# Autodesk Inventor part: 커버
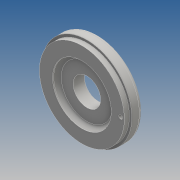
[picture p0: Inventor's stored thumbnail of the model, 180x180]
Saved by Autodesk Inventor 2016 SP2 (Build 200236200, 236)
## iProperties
Created: 2019-08
Part Number: 커버
Material: Generic
Document SubType Name: Modeling
Designer: EZ
Density: 1 g/cm^3
Appearance: Default
Author: EZ
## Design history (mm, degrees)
sketch "스케치1"
  geometry: C1 r 36 at (0, 0); 1 further point
  constraints: 1 centre point, 1 coincident
  dimensions: "d0" = 72 diameter of C1
extrude "돌출1" new body sketch "스케치1" distance "d1" = 9; taper "d2" = 0 deg
fillet "모깎기1" dims "d6" = 3
sketch "스케치3"
  geometry: C1 r 34 at (0, 0); 1 further point
  constraints: 1 centre point, 1 coincident
  dimensions: "d7" = 68 diameter of C1
extrude "돌출3" join sketch "스케치3" distance "d8" = 4; taper "d9" = 0 deg
sketch "스케치4"
  geometry: C1 r 11 at (0, 0); 1 further point
  constraints: 1 centre point, 1 coincident
  dimensions: "d10" = 22 diameter of C1
extrude "돌출4" cut sketch "스케치4" stored distance "d11" = 9; taper "d12" = 0 deg
sketch "스케치5"
  geometry: C1 r 23.5 at (0, 0); 1 further point
  constraints: 1 centre point, 1 coincident
  dimensions: "d13" = 47 diameter of C1
extrude "돌출5" cut sketch "스케치5" distance "d14" = 4; taper "d15" = 0 deg
fillet "모깎기2" dims "d16" = 3
sketch "스케치6"
  geometry: L1 (0, -38.373)-(0, 40.729); L2 (42.134, 0)-(-46.392, 0); C1 r 11 at (0, 0) reference; C2 r 33 at (0, 0) reference; C3 r 3.5 at (31, 0); 1 further point
  constraints: 4 end point, 3 point on line, 1 centre point, 1 horizontal, 1 vertical
  dimensions: "d17" = 7 diameter of C3; "d18" = 31 distance from line of L1 C3.centre
extrude "돌출6" cut sketch "스케치6" distance "d19" = 4; taper "d20" = 0 deg
sketch "스케치7"
  geometry: C1 r 3.5 at (0, 0) reference; 2 further points
  constraints: 1 coincident
hole "구멍1" sketch "스케치7" at (0, 0) diameter "d21" = 3; stored, may be unused: countersink angle "d25" = 90 deg, drill point angle "d27" = 118 deg; dims "d22" = 6, "d23" = 4, "d24" = 2, "d26" = 8
node "솔리드1"
node "투영된 루프1"
node "투영된 루프2"
